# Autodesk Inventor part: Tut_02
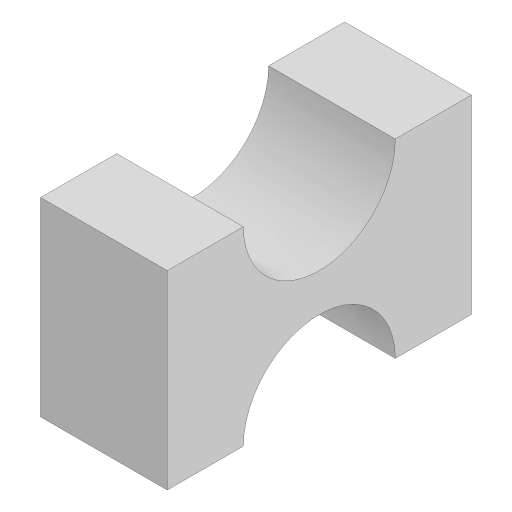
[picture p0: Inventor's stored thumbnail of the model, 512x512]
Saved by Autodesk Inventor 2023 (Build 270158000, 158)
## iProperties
Created: 2022-07
Part Number: Tut_02
Material: Generic
Document SubType Name: Modeling
Designer: LENOVO-CADCIM
Density: 1 g/cm^3
Appearance: Default
Author: LENOVO-CADCIM
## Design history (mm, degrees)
sketch "Sketch5"
  geometry: L1 (0, 0)-(0, 12); L2 (0, 0)-(12, 0); L3 (0, 0)-(0, -12); L4 (0, 12)-(0, 24); L5 (0, 12)-(12, 12); L6 (0, 24)-(-30, 24); L7 (-30, 24)-(-30, 12); L8 (-30, 12)-(-30, -12); L9 (-30, 12)-(-6, 12); L10 (-30, -12)-(-30, -24); L11 (-30, -12)-(-18, -12); L12 (-30, -24)-(0, -24); L13 (0, -24)-(0, -12); L14 (0, -24)-(12, -24); A1 r 12 centre (0, 0) between (0, 12) and (0, -12); A2 r 12 centre (-30, 0) between (-30, -12) and (-30, 12); 1 further point
  constraints: 28 end point, 8 perpendicular, 5 horizontal, 4 point on circle, 2 centre point, 2 vertical, 1 coincident
  dimensions: "d0" = 12 radius of A1; "d1" = 90 deg angle of L2 L1; "d2" = 180 deg angle of L3 L1; "d3" = 12 distance of L1.end L4.end; "d4" = 90 deg angle of L5 L4 (derived); "d5" = 30 distance of L4.end L6.end; "d6" = 90 deg angle of L6 L4 (derived); "d7" = 12 distance of L6.end L7.end; "d8" = 90 deg angle of L7 L6 (derived); "d9" = 24 distance of L7.end L8.end; "d10" = 90 deg angle of L8 L9; "d11" = 12 radius of A2; "d12" = 12 distance of L8.end L10.end; "d13" = 90 deg angle of L10 L11 (derived); "d14" = 30 distance of L10.end L12.end; "d15" = 90 deg angle of L12 L10 (derived); "d16" = 12 distance of L12.end L3.end (derived); "d17" = 90 deg angle of L14 L13 (derived)
extrude "Extrusion1" new body sketch "Sketch5" distance "d18" = 20; taper "d19" = 0 deg
body "Solid1"
